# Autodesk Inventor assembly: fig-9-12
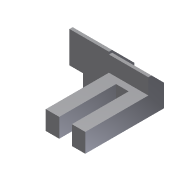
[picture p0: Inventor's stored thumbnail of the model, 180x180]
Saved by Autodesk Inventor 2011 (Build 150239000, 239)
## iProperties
Shininess: 64.0
Length Units: 11269
Angle Units: 11279
Time Units: 11290
Mass Units: 11283
Length Display Precision: 3
Angle Display Precision: 2
Created: 2002-01
Part Number: fig-9-12
Document SubType Name: Assembly
Designer: ***
Density: 0.0
Volumn: 0.0
Area: 0.0
PropertySet Name: Model Information
Control State: 0
Master: False
Checked Out: False
Author: ***
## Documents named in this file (3)
- C:\Users\CADSoft\Desktop\part files\c09-inv-2011-prt\fig-9-12.iam
- C:\Users\CADSoft\Desktop\part files\c09-inv-2011-prt\Part3.ipt
- C:\Users\CADSoft\Desktop\part files\c09-inv-2011-prt\Part4.ipt
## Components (2 placed, 2 different names)
1. Part3:1 — Flush:1, Flush:2, Flush:3, Mate:1
2. Part4:1 — Flush:1, Flush:2, Flush:3, Mate:1
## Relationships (4: Flush 3, Mate 1)
- Flush:1: Part3:1 ↔ Part4:1
- Flush:2: Part3:1 ↔ Part4:1
- Flush:3: Part3:1 ↔ Part4:1
- Mate:1: Part3:1 ↔ Part4:1
